// Mitsubishi GX Works2 project: FX3G_COM3_RD3A - 副本   PLC: FX3G

PROGRAM MAIN
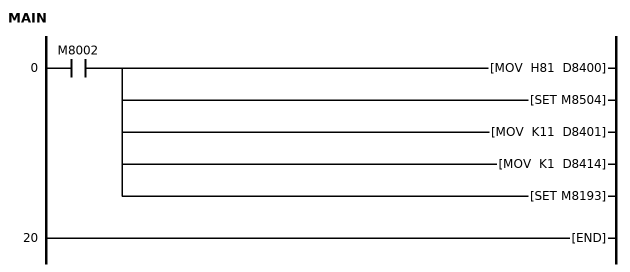
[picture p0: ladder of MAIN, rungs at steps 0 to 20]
0     LD      M8002
      MOV     H81 D8400
        [note] 通讯设定9600 8 N 1
      SET     M8504
      MOV     K11 D8401
        [note] 设置从站
      MOV     K1 D8414
        [note] 从站站号
      SET     M8193
        [note] on:其他协议协议off:编程口协议
20    END
END_PROGRAM

// device comments not shown above
D200  ; 写入数量，1个
D211  ; 转速
M2  ; 反转
M3  ; 停止
